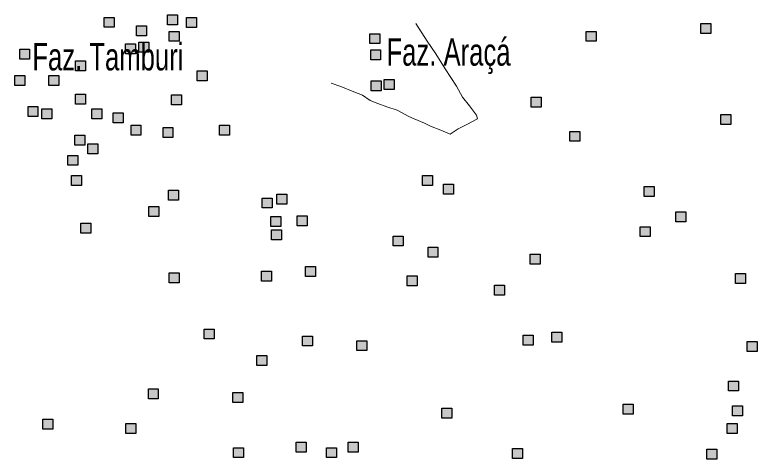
# Model space of a CAD drawing. Extents: x 445.4 to 500, y 8728.7 to 8784.
# Drawn here: x 476.154 to 480.489, y 8757.804 to 8760.399 of the extents above; entities that cross this region are included whole.
import ezdxf

# ---------------------------------------------------------------- set-up
doc = ezdxf.new("R2010")
doc.units = 0
doc.header["$LTSCALE"] = 0.064
doc.linetypes.add('DOT_DASHED', pattern=[7.7, 5, -1.2, 0.3, -1.2])
doc.layers.add('2', color=7, linetype='Continuous', lineweight=25)
doc.layers.add('22', color=7, linetype='DOT_DASHED', lineweight=13)
doc.layers.add('61', color=7, linetype='Continuous')

msp = doc.modelspace()

# ---------------------------------------------------------------- hatches: boundary and pattern name
at = {"layer": '2'}
for points in [[(477.0457, 8760.3988), (477.1037, 8760.3988), (477.1037, 8760.3408), (477.0457, 8760.3408)], [(476.6755, 8760.3839), (476.7335, 8760.3839), (476.7335, 8760.3259), (476.6755, 8760.3259)], [(477.1559, 8760.3835), (477.2139, 8760.3835), (477.2139, 8760.3255), (477.1559, 8760.3255)], [(476.8642, 8760.3341), (476.9222, 8760.3341), (476.9222, 8760.2761), (476.8642, 8760.2761)], [(480.1598, 8760.3476), (480.2178, 8760.3476), (480.2178, 8760.2896), (480.1598, 8760.2896)], [(477.0557, 8760.3024), (477.1137, 8760.3024), (477.1137, 8760.2444), (477.0557, 8760.2444)], [(478.2277, 8760.2888), (478.2857, 8760.2888), (478.2857, 8760.2308), (478.2277, 8760.2308)], [(479.4901, 8760.3024), (479.5481, 8760.3024), (479.5481, 8760.2444), (479.4901, 8760.2444)], [(476.8009, 8760.2299), (476.8589, 8760.2299), (476.8589, 8760.1719), (476.8009, 8760.1719)], [(476.8778, 8760.239), (476.9358, 8760.239), (476.9358, 8760.181), (476.8778, 8760.181)], [(476.1823, 8760.1982), (476.2403, 8760.1982), (476.2403, 8760.1402), (476.1823, 8760.1402)], [(478.2322, 8760.1937), (478.2902, 8760.1937), (478.2902, 8760.1357), (478.2322, 8760.1357)], [(476.5081, 8760.1303), (476.5661, 8760.1303), (476.5661, 8760.0723), (476.5081, 8760.0723)], [(477.2186, 8760.0715), (477.2766, 8760.0715), (477.2766, 8760.0135), (477.2186, 8760.0135)], [(476.1538, 8760.0443), (476.2118, 8760.0443), (476.2118, 8759.9863), (476.1538, 8759.9863)], [(476.3529, 8760.0443), (476.4109, 8760.0443), (476.4109, 8759.9863), (476.3529, 8759.9863)], [(478.2349, 8760.0134), (478.2929, 8760.0134), (478.2929, 8759.9554), (478.2349, 8759.9554)], [(478.3109, 8760.0211), (478.3689, 8760.0211), (478.3689, 8759.9631), (478.3109, 8759.9631)], [(476.5081, 8759.9357), (476.5661, 8759.9357), (476.5661, 8759.8777), (476.5081, 8759.8777)], [(477.0693, 8759.9311), (477.1273, 8759.9311), (477.1273, 8759.8731), (477.0693, 8759.8731)], [(479.1689, 8759.9175), (479.2269, 8759.9175), (479.2269, 8759.8595), (479.1689, 8759.8595)], [(476.2307, 8759.8632), (476.2887, 8759.8632), (476.2887, 8759.8052), (476.2307, 8759.8052)], [(476.3122, 8759.8496), (476.3702, 8759.8496), (476.3702, 8759.7916), (476.3122, 8759.7916)], [(476.6031, 8759.8496), (476.6611, 8759.8496), (476.6611, 8759.7916), (476.6031, 8759.7916)], [(476.7285, 8759.827), (476.7865, 8759.827), (476.7865, 8759.769), (476.7285, 8759.769)], [(480.2775, 8759.8162), (480.3355, 8759.8162), (480.3355, 8759.7582), (480.2775, 8759.7582)], [(476.8325, 8759.7546), (476.8905, 8759.7546), (476.8905, 8759.6966), (476.8325, 8759.6966)], [(477.3498, 8759.7546), (477.4078, 8759.7546), (477.4078, 8759.6966), (477.3498, 8759.6966)], [(477.0195, 8759.741), (477.0775, 8759.741), (477.0775, 8759.683), (477.0195, 8759.683)], [(479.3951, 8759.7183), (479.4531, 8759.7183), (479.4531, 8759.6603), (479.3951, 8759.6603)], [(476.5036, 8759.6957), (476.5616, 8759.6957), (476.5616, 8759.6377), (476.5036, 8759.6377)], [(476.5805, 8759.6459), (476.6385, 8759.6459), (476.6385, 8759.5879), (476.5805, 8759.5879)], [(476.4629, 8759.578), (476.5209, 8759.578), (476.5209, 8759.52), (476.4629, 8759.52)], [(476.4855, 8759.4603), (476.5435, 8759.4603), (476.5435, 8759.4023), (476.4855, 8759.4023)], [(478.5354, 8759.4603), (478.5934, 8759.4603), (478.5934, 8759.4023), (478.5354, 8759.4023)], [(478.6575, 8759.4105), (478.7155, 8759.4105), (478.7155, 8759.3525), (478.6575, 8759.3525)], [(477.0512, 8759.3742), (477.1092, 8759.3742), (477.1092, 8759.3162), (477.0512, 8759.3162)], [(479.8295, 8759.3969), (479.8875, 8759.3969), (479.8875, 8759.3389), (479.8295, 8759.3389)], [(477.5987, 8759.329), (477.6567, 8759.329), (477.6567, 8759.271), (477.5987, 8759.271)], [(477.6847, 8759.3516), (477.7427, 8759.3516), (477.7427, 8759.2936), (477.6847, 8759.2936)], [(476.9366, 8759.2792), (476.9946, 8759.2792), (476.9946, 8759.2212), (476.9366, 8759.2212)], [(480.015, 8759.2475), (480.073, 8759.2475), (480.073, 8759.1895), (480.015, 8759.1895)], [(477.6485, 8759.2203), (477.7065, 8759.2203), (477.7065, 8759.1623), (477.6485, 8759.1623)], [(477.8023, 8759.2248), (477.8603, 8759.2248), (477.8603, 8759.1668), (477.8023, 8759.1668)], [(476.5398, 8759.1813), (476.5978, 8759.1813), (476.5978, 8759.1233), (476.5398, 8759.1233)], [(477.653, 8759.1433), (477.711, 8759.1433), (477.711, 8759.0853), (477.653, 8759.0853)], [(479.8069, 8759.1615), (479.8649, 8759.1615), (479.8649, 8759.1035), (479.8069, 8759.1035)], [(478.3634, 8759.1071), (478.4214, 8759.1071), (478.4214, 8759.0491), (478.3634, 8759.0491)], [(478.567, 8759.042), (478.625, 8759.042), (478.625, 8758.984), (478.567, 8758.984)], [(479.1643, 8759.0012), (479.2223, 8759.0012), (479.2223, 8758.9432), (479.1643, 8758.9432)], [(477.8521, 8758.9288), (477.9101, 8758.9288), (477.9101, 8758.8708), (477.8521, 8758.8708)], [(477.0557, 8758.8926), (477.1137, 8758.8926), (477.1137, 8758.8346), (477.0557, 8758.8346)], [(477.5942, 8758.9016), (477.6522, 8758.9016), (477.6522, 8758.8436), (477.5942, 8758.8436)], [(480.3635, 8758.888), (480.4215, 8758.888), (480.4215, 8758.83), (480.3635, 8758.83)], [(478.4449, 8758.8745), (478.5029, 8758.8745), (478.5029, 8758.8165), (478.4449, 8758.8165)], [(478.9562, 8758.8201), (479.0142, 8758.8201), (479.0142, 8758.7621), (478.9562, 8758.7621)], [(477.2593, 8758.5638), (477.3173, 8758.5638), (477.3173, 8758.5058), (477.2593, 8758.5058)], [(479.291, 8758.5457), (479.349, 8758.5457), (479.349, 8758.4877), (479.291, 8758.4877)], [(477.834, 8758.5231), (477.892, 8758.5231), (477.892, 8758.4651), (477.834, 8758.4651)], [(478.1507, 8758.4959), (478.2087, 8758.4959), (478.2087, 8758.4379), (478.1507, 8758.4379)], [(479.1236, 8758.5276), (479.1816, 8758.5276), (479.1816, 8758.4696), (479.1236, 8758.4696)], [(480.4313, 8758.4914), (480.4893, 8758.4914), (480.4893, 8758.4334), (480.4313, 8758.4334)], [(477.567, 8758.4099), (477.625, 8758.4099), (477.625, 8758.3519), (477.567, 8758.3519)], [(480.3227, 8758.2605), (480.3807, 8758.2605), (480.3807, 8758.2025), (480.3227, 8758.2025)], [(476.9335, 8758.2152), (476.9915, 8758.2152), (476.9915, 8758.1572), (476.9335, 8758.1572)], [(477.4267, 8758.1926), (477.4847, 8758.1926), (477.4847, 8758.1346), (477.4267, 8758.1346)], [(478.6485, 8758.102), (478.7065, 8758.102), (478.7065, 8758.044), (478.6485, 8758.044)], [(479.7073, 8758.1247), (479.7653, 8758.1247), (479.7653, 8758.0667), (479.7073, 8758.0667)], [(480.3454, 8758.1156), (480.4034, 8758.1156), (480.4034, 8758.0576), (480.3454, 8758.0576)], [(476.3181, 8758.0369), (476.3761, 8758.0369), (476.3761, 8757.9789), (476.3181, 8757.9789)], [(476.8023, 8758.0115), (476.8603, 8758.0115), (476.8603, 8757.9535), (476.8023, 8757.9535)], [(480.3137, 8758.0115), (480.3717, 8758.0115), (480.3717, 8757.9535), (480.3137, 8757.9535)], [(477.7978, 8757.9028), (477.8558, 8757.9028), (477.8558, 8757.8448), (477.7978, 8757.8448)], [(478.101, 8757.9028), (478.159, 8757.9028), (478.159, 8757.8448), (478.101, 8757.8448)], [(477.4313, 8757.8711), (477.4893, 8757.8711), (477.4893, 8757.8131), (477.4313, 8757.8131)], [(477.9743, 8757.8711), (478.0323, 8757.8711), (478.0323, 8757.8131), (477.9743, 8757.8131)], [(479.0603, 8757.8666), (479.1183, 8757.8666), (479.1183, 8757.8086), (479.0603, 8757.8086)], [(480.196, 8757.8621), (480.254, 8757.8621), (480.254, 8757.8041), (480.196, 8757.8041)]]:
    msp.add_hatch(color=256, dxfattribs=at).paths.add_polyline_path(points)

# ---------------------------------------------------------------- linework, layer by layer
for points in [[(477.0457, 8760.3988), (477.1037, 8760.3988), (477.1037, 8760.3408), (477.0457, 8760.3408)], [(476.6755, 8760.3839), (476.7335, 8760.3839), (476.7335, 8760.3259), (476.6755, 8760.3259)], [(477.1559, 8760.3835), (477.2139, 8760.3835), (477.2139, 8760.3255), (477.1559, 8760.3255)], [(476.8642, 8760.3341), (476.9222, 8760.3341), (476.9222, 8760.2761), (476.8642, 8760.2761)], [(480.1598, 8760.3476), (480.2178, 8760.3476), (480.2178, 8760.2896), (480.1598, 8760.2896)], [(477.0557, 8760.3024), (477.1137, 8760.3024), (477.1137, 8760.2444), (477.0557, 8760.2444)], [(478.2277, 8760.2888), (478.2857, 8760.2888), (478.2857, 8760.2308), (478.2277, 8760.2308)], [(479.4901, 8760.3024), (479.5481, 8760.3024), (479.5481, 8760.2444), (479.4901, 8760.2444)], [(476.8009, 8760.2299), (476.8589, 8760.2299), (476.8589, 8760.1719), (476.8009, 8760.1719)], [(476.8778, 8760.239), (476.9358, 8760.239), (476.9358, 8760.181), (476.8778, 8760.181)], [(476.1823, 8760.1982), (476.2403, 8760.1982), (476.2403, 8760.1402), (476.1823, 8760.1402)], [(478.2322, 8760.1937), (478.2902, 8760.1937), (478.2902, 8760.1357), (478.2322, 8760.1357)], [(476.5081, 8760.1303), (476.5661, 8760.1303), (476.5661, 8760.0723), (476.5081, 8760.0723)], [(477.2186, 8760.0715), (477.2766, 8760.0715), (477.2766, 8760.0135), (477.2186, 8760.0135)], [(476.1538, 8760.0443), (476.2118, 8760.0443), (476.2118, 8759.9863), (476.1538, 8759.9863)], [(476.3529, 8760.0443), (476.4109, 8760.0443), (476.4109, 8759.9863), (476.3529, 8759.9863)], [(478.2349, 8760.0134), (478.2929, 8760.0134), (478.2929, 8759.9554), (478.2349, 8759.9554)], [(478.3109, 8760.0211), (478.3689, 8760.0211), (478.3689, 8759.9631), (478.3109, 8759.9631)], [(476.5081, 8759.9357), (476.5661, 8759.9357), (476.5661, 8759.8777), (476.5081, 8759.8777)], [(477.0693, 8759.9311), (477.1273, 8759.9311), (477.1273, 8759.8731), (477.0693, 8759.8731)], [(479.1689, 8759.9175), (479.2269, 8759.9175), (479.2269, 8759.8595), (479.1689, 8759.8595)], [(476.2307, 8759.8632), (476.2887, 8759.8632), (476.2887, 8759.8052), (476.2307, 8759.8052)], [(476.3122, 8759.8496), (476.3702, 8759.8496), (476.3702, 8759.7916), (476.3122, 8759.7916)], [(476.6031, 8759.8496), (476.6611, 8759.8496), (476.6611, 8759.7916), (476.6031, 8759.7916)], [(476.7285, 8759.827), (476.7865, 8759.827), (476.7865, 8759.769), (476.7285, 8759.769)], [(480.2775, 8759.8162), (480.3355, 8759.8162), (480.3355, 8759.7582), (480.2775, 8759.7582)], [(476.8325, 8759.7546), (476.8905, 8759.7546), (476.8905, 8759.6966), (476.8325, 8759.6966)], [(477.3498, 8759.7546), (477.4078, 8759.7546), (477.4078, 8759.6966), (477.3498, 8759.6966)], [(477.0195, 8759.741), (477.0775, 8759.741), (477.0775, 8759.683), (477.0195, 8759.683)], [(479.3951, 8759.7183), (479.4531, 8759.7183), (479.4531, 8759.6603), (479.3951, 8759.6603)], [(476.5036, 8759.6957), (476.5616, 8759.6957), (476.5616, 8759.6377), (476.5036, 8759.6377)], [(476.5805, 8759.6459), (476.6385, 8759.6459), (476.6385, 8759.5879), (476.5805, 8759.5879)], [(476.4629, 8759.578), (476.5209, 8759.578), (476.5209, 8759.52), (476.4629, 8759.52)], [(476.4855, 8759.4603), (476.5435, 8759.4603), (476.5435, 8759.4023), (476.4855, 8759.4023)], [(478.5354, 8759.4603), (478.5934, 8759.4603), (478.5934, 8759.4023), (478.5354, 8759.4023)], [(478.6575, 8759.4105), (478.7155, 8759.4105), (478.7155, 8759.3525), (478.6575, 8759.3525)], [(477.0512, 8759.3742), (477.1092, 8759.3742), (477.1092, 8759.3162), (477.0512, 8759.3162)], [(479.8295, 8759.3969), (479.8875, 8759.3969), (479.8875, 8759.3389), (479.8295, 8759.3389)], [(477.5987, 8759.329), (477.6567, 8759.329), (477.6567, 8759.271), (477.5987, 8759.271)], [(477.6847, 8759.3516), (477.7427, 8759.3516), (477.7427, 8759.2936), (477.6847, 8759.2936)], [(476.9366, 8759.2792), (476.9946, 8759.2792), (476.9946, 8759.2212), (476.9366, 8759.2212)], [(480.015, 8759.2475), (480.073, 8759.2475), (480.073, 8759.1895), (480.015, 8759.1895)], [(477.6485, 8759.2203), (477.7065, 8759.2203), (477.7065, 8759.1623), (477.6485, 8759.1623)], [(477.8023, 8759.2248), (477.8603, 8759.2248), (477.8603, 8759.1668), (477.8023, 8759.1668)], [(476.5398, 8759.1813), (476.5978, 8759.1813), (476.5978, 8759.1233), (476.5398, 8759.1233)], [(477.653, 8759.1433), (477.711, 8759.1433), (477.711, 8759.0853), (477.653, 8759.0853)], [(479.8069, 8759.1615), (479.8649, 8759.1615), (479.8649, 8759.1035), (479.8069, 8759.1035)], [(478.3634, 8759.1071), (478.4214, 8759.1071), (478.4214, 8759.0491), (478.3634, 8759.0491)], [(478.567, 8759.042), (478.625, 8759.042), (478.625, 8758.984), (478.567, 8758.984)], [(479.1643, 8759.0012), (479.2223, 8759.0012), (479.2223, 8758.9432), (479.1643, 8758.9432)], [(477.8521, 8758.9288), (477.9101, 8758.9288), (477.9101, 8758.8708), (477.8521, 8758.8708)], [(477.0557, 8758.8926), (477.1137, 8758.8926), (477.1137, 8758.8346), (477.0557, 8758.8346)], [(477.5942, 8758.9016), (477.6522, 8758.9016), (477.6522, 8758.8436), (477.5942, 8758.8436)], [(480.3635, 8758.888), (480.4215, 8758.888), (480.4215, 8758.83), (480.3635, 8758.83)], [(478.4449, 8758.8745), (478.5029, 8758.8745), (478.5029, 8758.8165), (478.4449, 8758.8165)], [(478.9562, 8758.8201), (479.0142, 8758.8201), (479.0142, 8758.7621), (478.9562, 8758.7621)], [(477.2593, 8758.5638), (477.3173, 8758.5638), (477.3173, 8758.5058), (477.2593, 8758.5058)], [(479.291, 8758.5457), (479.349, 8758.5457), (479.349, 8758.4877), (479.291, 8758.4877)], [(477.834, 8758.5231), (477.892, 8758.5231), (477.892, 8758.4651), (477.834, 8758.4651)], [(478.1507, 8758.4959), (478.2087, 8758.4959), (478.2087, 8758.4379), (478.1507, 8758.4379)], [(479.1236, 8758.5276), (479.1816, 8758.5276), (479.1816, 8758.4696), (479.1236, 8758.4696)], [(480.4313, 8758.4914), (480.4893, 8758.4914), (480.4893, 8758.4334), (480.4313, 8758.4334)], [(477.567, 8758.4099), (477.625, 8758.4099), (477.625, 8758.3519), (477.567, 8758.3519)], [(480.3227, 8758.2605), (480.3807, 8758.2605), (480.3807, 8758.2025), (480.3227, 8758.2025)], [(476.9335, 8758.2152), (476.9915, 8758.2152), (476.9915, 8758.1572), (476.9335, 8758.1572)], [(477.4267, 8758.1926), (477.4847, 8758.1926), (477.4847, 8758.1346), (477.4267, 8758.1346)], [(478.6485, 8758.102), (478.7065, 8758.102), (478.7065, 8758.044), (478.6485, 8758.044)], [(479.7073, 8758.1247), (479.7653, 8758.1247), (479.7653, 8758.0667), (479.7073, 8758.0667)], [(480.3454, 8758.1156), (480.4034, 8758.1156), (480.4034, 8758.0576), (480.3454, 8758.0576)], [(476.3181, 8758.0369), (476.3761, 8758.0369), (476.3761, 8757.9789), (476.3181, 8757.9789)], [(476.8023, 8758.0115), (476.8603, 8758.0115), (476.8603, 8757.9535), (476.8023, 8757.9535)], [(480.3137, 8758.0115), (480.3717, 8758.0115), (480.3717, 8757.9535), (480.3137, 8757.9535)], [(477.7978, 8757.9028), (477.8558, 8757.9028), (477.8558, 8757.8448), (477.7978, 8757.8448)], [(478.101, 8757.9028), (478.159, 8757.9028), (478.159, 8757.8448), (478.101, 8757.8448)], [(477.4313, 8757.8711), (477.4893, 8757.8711), (477.4893, 8757.8131), (477.4313, 8757.8131)], [(477.9743, 8757.8711), (478.0323, 8757.8711), (478.0323, 8757.8131), (477.9743, 8757.8131)], [(479.0603, 8757.8666), (479.1183, 8757.8666), (479.1183, 8757.8086), (479.0603, 8757.8086)], [(480.196, 8757.8621), (480.254, 8757.8621), (480.254, 8757.8041), (480.196, 8757.8041)]]:
    msp.add_lwpolyline(points, close=True, dxfattribs=at)
at = {"layer": '22'}
msp.add_lwpolyline([(478.4964, 8760.3483), (478.5614, 8760.246), (478.6133, 8760.1718), (478.6671, 8760.0828), (478.7338, 8759.9826), (478.769, 8759.9177), (478.8098, 8759.8677), (478.8506, 8759.812), (478.8561, 8759.7916), (478.7931, 8759.7583), (478.7431, 8759.7341), (478.6967, 8759.7026), (478.6411, 8759.7249), (478.5818, 8759.749), (478.5466, 8759.7657), (478.4854, 8759.7916), (478.4558, 8759.8046), (478.3872, 8759.8417), (478.3261, 8759.8621), (478.2742, 8759.8807), (478.2297, 8759.8992), (478.1852, 8759.9289), (478.1333, 8759.9493), (478.0584, 8759.9797), (478.0005, 8760.0005)], dxfattribs=at)

# ---------------------------------------------------------------- texts
at = {"layer": '61', "width": 0.7}
for s, p in [('Faz. Araçá', (478.3246, 8760.1021)), ('Faz. Tamburi', (476.256, 8760.0745))]:
    msp.add_text(s, height=0.16, dxfattribs=at).set_placement(p)

doc.saveas('drawing.dxf')
